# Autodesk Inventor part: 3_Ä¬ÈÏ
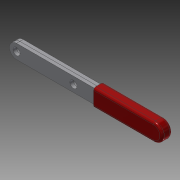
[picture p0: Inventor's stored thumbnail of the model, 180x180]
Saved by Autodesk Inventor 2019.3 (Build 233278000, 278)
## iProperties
Created: 2010-06
Part Number: 3_Ä¬ÈÏ
Material: Ogólny
Document SubType Name: Modeling
Designer: CADENGINEERING4
Density: 1 g/cm^3
Appearance: Domyślna
Author: CADENGINEERING4
Revision Number: ÈÎºÎ
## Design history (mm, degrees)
feature "NONE"
feature "NONE:1"
feature "NONE:2"
node "Bryła1"
node "Bryła2"
node "Bryła3"
